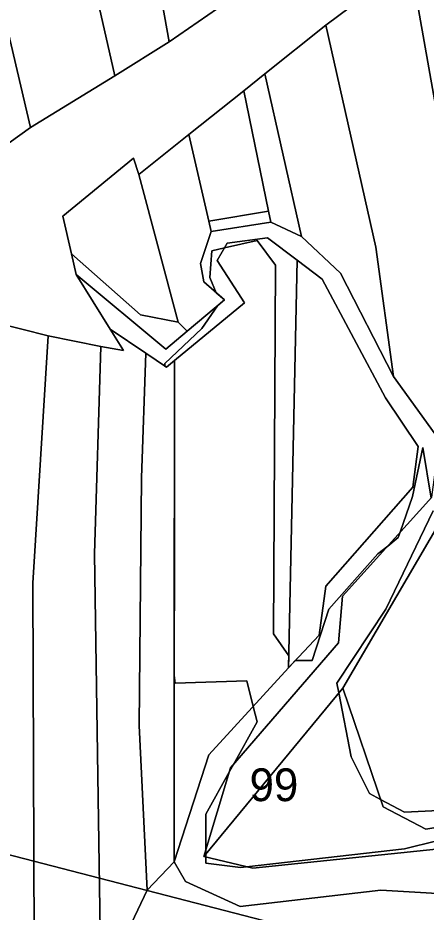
# Model space of a CAD drawing. Extents: x -502026 to -497664, y -1143484 to -1138019.
# Drawn here: x -499356.4 to -499256.7, y -1140803.4 to -1140585.2 of the extents above; entities that cross this region are included whole.
import ezdxf

# ---------------------------------------------------------------- set-up
doc = ezdxf.new("R2010")
doc.units = 0
for name, color, linetype in [('25', 7, 'Continuous'), ('37', 7, 'Continuous'), ('43', 7, 'Continuous'), ('49', 7, 'Continuous'), ('55', 7, 'Continuous'), ('62', 7, 'Continuous'), ('7', 7, 'Continuous')]:
    doc.layers.add(name, color=color, linetype=linetype)

msp = doc.modelspace()

# ---------------------------------------------------------------- linework, layer by layer
at = {"layer": '25'}
for points in [[(-499305.3, -1140581.24), (-499319.49, -1140590.99), (-499328.23, -1140541.95), (-499333.65, -1140517.3), (-499339.19, -1140492.06), (-499326.12, -1140487.86), (-499325.8, -1140489.3), (-499313.32, -1140541.58)], [(-499370.91, -1140536.96), (-499370.23, -1140539.85), (-499353.36, -1140611.94), (-499369.03, -1140623.13), (-499373.1, -1140611.24), (-499409.47, -1140505.06), (-499403.15, -1140504.27), (-499393.71, -1140535.09), (-499386.6, -1140533.43), (-499385.01, -1140540.25), (-499371.38, -1140537.07)], [(-499319.49, -1140590.99), (-499332.72, -1140599.3), (-499347.33, -1140535.13), (-499349.09, -1140527.38), (-499348.23, -1140527.18), (-499339.13, -1140524.95), (-499340.51, -1140518.85), (-499333.65, -1140517.3), (-499328.23, -1140541.95)], [(-499332.72, -1140599.3), (-499353.36, -1140611.94), (-499370.23, -1140539.85), (-499366.7, -1140539.16), (-499348.09, -1140535.29), (-499347.33, -1140535.13)]]:
    msp.add_lwpolyline(points, close=True, dxfattribs=at)
at = {"layer": '37'}
msp.add_lwpolyline([(-499290.33, -1140743.77), (-499288.22, -1140644.33), (-499282.07, -1140648.94), (-499266.63, -1140677.91), (-499258.63, -1140689.76), (-499259.94, -1140699.73), (-499281.23, -1140723.83), (-499282.82, -1140735.82)], close=True, dxfattribs=at)
at = {"layer": '43'}
for points in [[(-499288.22, -1140644.33), (-499290.33, -1140743.77), (-499309.77, -1140765.06), (-499318.22, -1140791.11), (-499318.17, -1140668.78), (-499301.07, -1140654.71), (-499307.72, -1140644.36), (-499305.28, -1140640.15), (-499295.48, -1140638.88)], [(-499277.06, -1140748.76), (-499311.03, -1140789.86), (-499304.44, -1140768.17), (-499278.12, -1140737.7), (-499277.15, -1140726.28), (-499255.28, -1140702.14), (-499253.41, -1140688.26), (-499251.1, -1140688), (-499250.63, -1140703.66)], [(-499098.45, -1140792.47), (-499169.08, -1140829.79), (-499220.72, -1140841.83), (-499256.21, -1140836.16), (-499277.72, -1140829.32), (-499287.7, -1140819.38), (-499306.66, -1140814.44), (-499352.42, -1140810.64), (-499336.3, -1140807.98), (-499328.65, -1140806.13), (-499324.82, -1140798.07), (-499318.22, -1140791.11), (-499315.45, -1140795.96), (-499302.12, -1140802.04), (-499267.8, -1140798.07), (-499244.32, -1140799.43), (-499230, -1140808.8), (-499223.13, -1140810.06), (-499213.06, -1140806.58), (-499212.54, -1140813.69), (-499178.21, -1140807.73), (-499161.8, -1140797.63), (-499134.65, -1140793.45), (-499107.41, -1140785.15)]]:
    msp.add_lwpolyline(points, close=True, dxfattribs=at)
at = {"layer": '49'}
for points in [[(-499244.32, -1140799.43), (-499267.8, -1140798.07), (-499302.12, -1140802.04), (-499315.45, -1140795.96), (-499318.22, -1140791.11), (-499309.77, -1140765.06), (-499290.33, -1140743.77), (-499282.82, -1140735.82), (-499281.23, -1140723.83), (-499259.94, -1140699.73), (-499258.63, -1140689.76), (-499266.63, -1140677.91), (-499282.07, -1140648.94), (-499288.22, -1140644.33), (-499295.48, -1140638.88), (-499305.28, -1140640.15), (-499307.72, -1140644.36), (-499301.07, -1140654.71), (-499318.17, -1140668.78), (-499320.15, -1140670.38), (-499325.18, -1140666.98), (-499333.87, -1140661.11), (-499342.17, -1140647.8), (-499320.25, -1140665.99), (-499315.04, -1140661.62), (-499305.93, -1140653.99), (-499310.96, -1140649.6), (-499311.8, -1140645.11), (-499309.22, -1140637.3), (-499294.64, -1140635.04), (-499287.15, -1140638.53), (-499277.6, -1140647.5), (-499264.63, -1140672.68), (-499253.41, -1140688.26)], [(-499255.28, -1140702.14), (-499277.15, -1140726.28), (-499278.12, -1140737.7), (-499304.44, -1140768.17), (-499311.03, -1140789.86), (-499299.02, -1140792.7), (-499254.28, -1140788.04)]]:
    msp.add_lwpolyline(points, dxfattribs=at)
at = {"layer": '55'}
for points in [[(-499260.6, -1140571.56), (-499281.18, -1140586.94), (-499296.07, -1140598.84), (-499301.26, -1140602.98), (-499314.65, -1140613.66), (-499326.87, -1140623.41), (-499328.15, -1140619.37), (-499345.45, -1140633.59), (-499343.34, -1140642.72), (-499342.17, -1140647.8), (-499333.87, -1140661.11), (-499330.61, -1140666.33), (-499336.17, -1140665.33), (-499348.98, -1140662.77), (-499361.92, -1140659.52)], [(-499369.03, -1140623.13), (-499353.36, -1140611.94), (-499332.72, -1140599.3), (-499319.49, -1140590.99), (-499305.3, -1140581.24)]]:
    msp.add_lwpolyline(points, dxfattribs=at)
for points in [[(-499294.64, -1140635.04), (-499309.22, -1140637.3), (-499309.8, -1140634.76), (-499295.2, -1140632.31)], [(-499317.24, -1140659.42), (-499315.04, -1140661.62), (-499320.25, -1140665.99), (-499342.17, -1140647.8), (-499343.34, -1140642.72), (-499326.46, -1140657.64)], [(-499231.38, -1140783.18), (-499233.45, -1140783.49), (-499243.54, -1140786.63), (-499243.35, -1140783.68), (-499242.62, -1140783.74), (-499242.09, -1140775.8), (-499242.86, -1140775.72), (-499242.02, -1140760.36), (-499248.5, -1140759.99), (-499248.79, -1140765.28), (-499252.74, -1140765.06), (-499253.84, -1140782.67), (-499256.76, -1140783.21), (-499267.22, -1140777.72), (-499277.06, -1140748.76), (-499250.63, -1140703.66), (-499251.1, -1140688), (-499249.58, -1140687.83), (-499246.17, -1140705.68)], [(-499253.84, -1140782.67), (-499254.28, -1140788.04), (-499299.02, -1140792.7), (-499311.03, -1140789.86), (-499277.06, -1140748.76), (-499267.22, -1140777.72), (-499256.76, -1140783.21)]]:
    msp.add_lwpolyline(points, close=True, dxfattribs=at)
at = {"layer": '62'}
for points in [[(-499255.5, -1140702.38), (-499257.5, -1140690), (-499260, -1140702), (-499263.05, -1140710.72), (-499263.5, -1140712), (-499266.09, -1140714.07), (-499268.5, -1140716), (-499280.5, -1140729.5), (-499284.5, -1140742), (-499288.66, -1140742), (-499290.33, -1140743.77), (-499290.27, -1140740.89), (-499294, -1140735.5), (-499293.5, -1140645.5), (-499298, -1140639.5), (-499305.95, -1140641.31), (-499309, -1140642), (-499309.5, -1140648.5), (-499307.95, -1140652.23), (-499305.93, -1140653.99), (-499307.64, -1140655.42), (-499311.5, -1140661), (-499320.5, -1140669.5), (-499320.52, -1140670.13), (-499320.15, -1140670.38), (-499318.17, -1140668.78), (-499318.2, -1140745.69), (-499318, -1140747.5), (-499300.5, -1140747), (-499298.95, -1140753.21), (-499298, -1140757), (-499303.78, -1140767.41), (-499304.72, -1140769.1), (-499310.5, -1140779.5), (-499310.5, -1140788.11), (-499310.5, -1140789.22), (-499310.5, -1140789.98), (-499310.5, -1140791.5), (-499302, -1140792.5), (-499300.55, -1140792.34), (-499262, -1140788), (-499254.12, -1140786.03)], [(-499254.12, -1140786.03), (-499262, -1140788), (-499300.55, -1140792.34), (-499302, -1140792.5), (-499310.5, -1140791.5), (-499310.5, -1140789.98), (-499310.5, -1140789.22), (-499310.5, -1140788.11), (-499310.5, -1140779.5), (-499304.72, -1140769.1), (-499303.78, -1140767.41), (-499298, -1140757), (-499298.95, -1140753.21), (-499300.5, -1140747), (-499318, -1140747.5), (-499318.2, -1140745.69), (-499318.17, -1140668.78), (-499320.15, -1140670.38), (-499320.52, -1140670.13), (-499320.5, -1140669.5), (-499311.5, -1140661), (-499307.64, -1140655.42), (-499305.93, -1140653.99), (-499307.95, -1140652.23), (-499309.5, -1140648.5), (-499309, -1140642), (-499305.95, -1140641.31), (-499298, -1140639.5), (-499293.5, -1140645.5), (-499294, -1140735.5), (-499290.27, -1140740.89), (-499290.33, -1140743.77), (-499288.66, -1140742), (-499284.5, -1140742), (-499280.5, -1140729.5), (-499268.5, -1140716), (-499266.09, -1140714.07), (-499263.5, -1140712), (-499263.05, -1140710.72), (-499260, -1140702), (-499257.5, -1140690), (-499255.5, -1140702.38)], [(-499253.59, -1140778.64), (-499262, -1140779), (-499267.83, -1140775.91), (-499270.5, -1140774.5), (-499275, -1140765.5), (-499278.03, -1140749.93), (-499278.5, -1140747.5), (-499266.5, -1140729.5), (-499255, -1140705.5)], [(-499255, -1140705.5), (-499266.5, -1140729.5), (-499278.5, -1140747.5), (-499278.03, -1140749.93), (-499275, -1140765.5), (-499270.5, -1140774.5), (-499267.83, -1140775.91), (-499262, -1140779), (-499253.59, -1140778.64)], [(-499558, -1140718), (-499549.32, -1140718.52), (-499545, -1140718.79), (-499543.18, -1140718.9), (-499533.55, -1140719.48), (-499525, -1140720), (-499514.91, -1140722.69), (-499495.53, -1140727.86), (-499487.17, -1140730.09), (-499480, -1140732), (-499470.97, -1140736.77), (-499450.73, -1140747.47), (-499432.09, -1140757.32), (-499412.69, -1140767.57), (-499390.87, -1140779.11), (-499386.37, -1140781.48), (-499384.1, -1140782.68), (-499383.5, -1140783), (-499376.51, -1140784.81), (-499364.91, -1140787.81), (-499352.5, -1140791.02), (-499336.5, -1140795.15), (-499324.86, -1140798.16), (-499296.5, -1140805.5)], [(-499296.5, -1140805.5), (-499324.86, -1140798.16), (-499336.5, -1140795.15), (-499352.5, -1140791.02), (-499364.91, -1140787.81), (-499376.51, -1140784.81), (-499383.5, -1140783), (-499384.1, -1140782.68), (-499386.37, -1140781.48), (-499390.87, -1140779.11), (-499412.69, -1140767.57), (-499432.09, -1140757.32), (-499450.73, -1140747.47), (-499470.97, -1140736.77), (-499480, -1140732), (-499487.17, -1140730.09), (-499495.53, -1140727.86), (-499514.91, -1140722.69), (-499525, -1140720), (-499533.55, -1140719.48), (-499543.18, -1140718.9), (-499545, -1140718.79), (-499549.32, -1140718.52), (-499558, -1140718)]]:
    msp.add_lwpolyline(points, dxfattribs=at)
at = {"layer": '7'}
for points in [[(-499218.19, -1140781.23), (-499222.82, -1140781.91), (-499244.36, -1140663), (-499260.6, -1140571.56), (-499255.78, -1140568.6), (-499239.42, -1140658.77)], [(-499222.82, -1140781.91), (-499231.38, -1140783.18), (-499246.17, -1140705.68), (-499249.58, -1140687.83), (-499251.1, -1140688), (-499253.41, -1140688.26), (-499264.63, -1140672.68), (-499268.97, -1140641.12), (-499281.18, -1140586.94), (-499260.6, -1140571.56), (-499244.36, -1140663)], [(-499264.63, -1140672.68), (-499277.6, -1140647.5), (-499287.15, -1140638.53), (-499296.07, -1140598.84), (-499281.18, -1140586.94), (-499268.97, -1140641.12)], [(-499287.15, -1140638.53), (-499294.64, -1140635.04), (-499295.2, -1140632.31), (-499301.26, -1140602.98), (-499296.07, -1140598.84)], [(-499295.2, -1140632.31), (-499309.8, -1140634.76), (-499314.65, -1140613.66), (-499301.26, -1140602.98)], [(-499309.8, -1140634.76), (-499309.22, -1140637.3), (-499311.8, -1140645.11), (-499310.96, -1140649.6), (-499305.93, -1140653.99), (-499315.04, -1140661.62), (-499317.24, -1140659.42), (-499326.87, -1140623.41), (-499314.65, -1140613.66)], [(-499326.87, -1140623.41), (-499317.24, -1140659.42), (-499326.46, -1140657.64), (-499343.34, -1140642.72), (-499345.45, -1140633.59), (-499328.15, -1140619.37)], [(-499348.98, -1140662.77), (-499352.78, -1140723.14), (-499352.42, -1140810.64), (-499365.81, -1140811.09), (-499362.02, -1140713.37), (-499361.92, -1140659.52)], [(-499325.18, -1140666.98), (-499326.25, -1140697.39), (-499326.78, -1140757.9), (-499324.82, -1140798.07), (-499328.65, -1140806.13), (-499336.3, -1140807.98), (-499337.73, -1140716.01), (-499336.17, -1140665.33), (-499330.61, -1140666.33), (-499333.87, -1140661.11)], [(-499336.17, -1140665.33), (-499337.73, -1140716.01), (-499336.3, -1140807.98), (-499352.42, -1140810.64), (-499352.78, -1140723.14), (-499348.98, -1140662.77)], [(-499318.17, -1140668.78), (-499318.22, -1140791.11), (-499324.82, -1140798.07), (-499326.78, -1140757.9), (-499326.25, -1140697.39), (-499325.18, -1140666.98), (-499320.15, -1140670.38)]]:
    msp.add_lwpolyline(points, close=True, dxfattribs=at)

# ---------------------------------------------------------------- texts
at = {"layer": '62'}
msp.add_text('99', height=8, dxfattribs=at).set_placement((-499299.82, -1140776.33))

doc.saveas('drawing.dxf')
